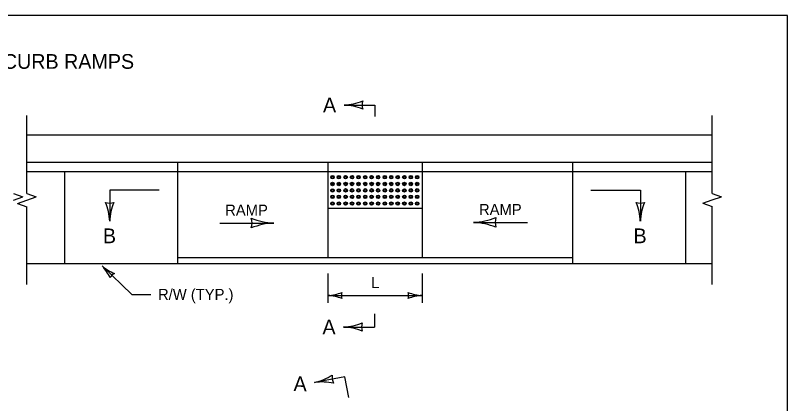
# Model space of a CAD drawing. Extents: x 49991.4 to 50021, y 49987.6 to 50011.4.
# Drawn here: x 50004.419 to 50008.615, y 50009.154 to 50011.263 of the extents above; entities that cross this region are included whole.
import ezdxf

# ---------------------------------------------------------------- set-up
doc = ezdxf.new("R2010")
doc.units = 0
for name, color, linetype in [('Level 1', 7, 'Continuous'), ('Level 2', 7, 'Continuous'), ('Level 3', 7, 'Continuous'), ('Level 6', 7, 'Continuous'), ('Level 8', 7, 'Continuous')]:
    doc.layers.add(name, color=color, linetype=linetype)

msp = doc.modelspace()

# ---------------------------------------------------------------- linework, layer by layer
at = {"layer": 'Level 1'}
for p, q in [((50008.2048, 50010.6129), (50004.4804, 50010.6129)), ((50008.2048, 50010.4629), (50004.4804, 50010.4629)), ((50005.2998, 50010.4629), (50005.2998, 50009.9129)), ((50006.1169, 50010.4629), (50006.117, 50009.9462)), ((50006.6283, 50010.4629), (50006.6284, 50009.9462)), ((50007.4459, 50010.4629), (50007.4458, 50009.9129)), ((50008.2048, 50010.4129), (50004.4804, 50010.4129)), ((50004.6865, 50009.9129), (50004.6863, 50010.4129)), ((50008.0591, 50010.4129), (50008.0591, 50009.9129)), ((50006.6283, 50010.2129), (50006.1169, 50010.2129)), ((50007.4458, 50009.9462), (50005.2998, 50009.9462)), ((50008.2048, 50009.9129), (50004.4804, 50009.9129))]:
    msp.add_line(p, q, dxfattribs=at)
msp.add_lwpolyline([(50008.6146, 50011.2628), (50000.3356, 50011.2628), (50000.3356, 50000.0624), (50008.6146, 50000.0624)], close=True, dxfattribs=at)
for points in [[(50008.6146, 50011.2628), (50000.3356, 50011.2628)], [(50008.6146, 50000.0624), (50008.6146, 50011.2628)]]:
    msp.add_lwpolyline(points, dxfattribs=at)
at = {"layer": 'Level 2'}
for centre in [(50006.3196, 50010.3122), (50006.3545, 50010.3122), (50006.3894, 50010.3122)]:
    msp.add_circle(centre, 0.00945, dxfattribs=at)
at = {"layer": 'Level 3'}
for p, q in [((50004.8898, 50009.9014), (50005.0518, 50009.7472)), ((50006.1171, 50009.8615), (50006.1171, 50009.7011)), ((50006.6285, 50009.8615), (50006.6285, 50009.7011)), ((50005.0518, 50009.7472), (50005.1536, 50009.7472)), ((50006.1171, 50009.7411), (50006.6285, 50009.7411))]:
    msp.add_line(p, q, dxfattribs=at)
for centre, radius, start, end in [((50006.1926, 50011.0723), 0.2964, 272.3605, 292.544), ((50006.1895, 50010.4658), 0.3107, 67.9228, 87.1727), ((50006.3758, 50010.7761), 0.073, 162.1388, 197.8612), ((50004.6348, 50010.133), 0.2964, 2.3605, 22.544), ((50004.931, 50010.3161), 0.073, 252.1388, 287.8612), ((50005.2413, 50010.1299), 0.3107, 157.9228, 177.1727), ((50007.5184, 50010.133), 0.2964, 2.3605, 22.544), ((50007.8146, 50010.3161), 0.073, 252.1388, 287.8612), ((50008.1249, 50010.1299), 0.3107, 157.9228, 177.1727), ((50005.6169, 50010.1348), 0.0876, 342.1388, 17.8612), ((50005.8404, 50010.5071), 0.3728, 247.9228, 267.1727), ((50006.8936, 50010.4938), 0.3557, 272.3605, 292.544), ((50007.1134, 50010.1384), 0.0876, 162.1388, 197.8612), ((50005.8367, 50009.7794), 0.3557, 92.3605, 112.544), ((50006.8898, 50009.766), 0.3728, 67.9228, 87.1727), ((50005.0363, 50010.0686), 0.2223, 228.7655, 248.949), ((50004.721, 50009.7408), 0.233, 24.3279, 43.5777), ((50004.9826, 50009.813), 0.0548, 118.5439, 154.2662), ((50006.1056, 50009.9738), 0.233, 272.8273, 292.0772), ((50006.1079, 50009.519), 0.2223, 67.456, 87.6395), ((50006.2453, 50009.7411), 0.0548, 162.1388, 197.8612), ((50006.6376, 50009.9632), 0.2223, 247.456, 267.6395), ((50006.5002, 50009.7411), 0.0548, 342.1388, 17.8612), ((50006.6399, 50009.5084), 0.233, 92.8273, 112.0772), ((50006.1896, 50009.8661), 0.2964, 272.3605, 292.544), ((50006.1865, 50009.2596), 0.3107, 67.9228, 87.1727), ((50006.3727, 50009.5699), 0.073, 162.1388, 197.8612), ((50005.9784, 50009.5575), 0.2964, 282.8123, 302.9958), ((50006.2123, 50009.2995), 0.073, 172.5907, 208.313), ((50006.0854, 50008.9605), 0.3107, 78.3747, 97.6245)]:
    msp.add_arc(centre, radius, start, end, dxfattribs=at)
at = {"layer": 'Level 6'}
for p, q in [((50006.2048, 50010.7761), (50006.3725, 50010.7761)), ((50006.3725, 50010.7761), (50006.3725, 50010.7129)), ((50004.4804, 50010.296), (50004.4804, 50010.7183)), ((50008.2048, 50010.2962), (50008.2048, 50010.7183)), ((50005.1143, 50010.3129), (50004.931, 50010.3129)), ((50004.931, 50010.3129), (50004.931, 50010.1452)), ((50005.1998, 50010.3129), (50004.931, 50010.3129)), ((50004.931, 50010.3129), (50004.931, 50010.1452)), ((50007.5459, 50010.3129), (50007.8146, 50010.3129)), ((50007.8146, 50010.3129), (50007.8146, 50010.1452)), ((50007.8146, 50010.3129), (50007.8146, 50010.1452)), ((50004.4081, 50010.296), (50004.4589, 50010.2778)), ((50004.4081, 50010.2598), (50004.4589, 50010.2778)), ((50004.4804, 50010.296), (50004.5312, 50010.2778)), ((50004.4804, 50010.2598), (50004.5312, 50010.2778)), ((50008.2048, 50010.2962), (50008.2556, 50010.278)), ((50008.2048, 50010.26), (50008.2556, 50010.278)), ((50004.4294, 50010.2417), (50004.4804, 50010.2598)), ((50004.4294, 50010.2417), (50004.4804, 50010.2237)), ((50008.1538, 50010.2419), (50008.2048, 50010.26)), ((50008.1538, 50010.2419), (50008.2048, 50010.2239)), ((50004.4804, 50009.8014), (50004.4804, 50010.2237)), ((50008.2048, 50009.8017), (50008.2048, 50010.2239)), ((50005.5289, 50010.1348), (50005.822, 50010.1348)), ((50006.9082, 50010.1384), (50007.2013, 50010.1384)), ((50006.3695, 50009.6411), (50006.3695, 50009.5699)), ((50006.2018, 50009.5699), (50006.3695, 50009.5699)), ((50006.2091, 50009.2989), (50006.0441, 50009.2684)), ((50006.2296, 50009.1876), (50006.2091, 50009.2989))]:
    msp.add_line(p, q, dxfattribs=at)
at = {"layer": 'Level 8'}
for centre, radius in [((50006.1414, 50010.3838), 0.00945), ((50006.1414, 50010.347), 0.00945), ((50006.1414, 50010.3838), 0.00525), ((50006.1763, 50010.3838), 0.00945), ((50006.1763, 50010.347), 0.00945), ((50006.1763, 50010.3838), 0.00525), ((50006.213, 50010.3838), 0.00945), ((50006.2131, 50010.3471), 0.00945), ((50006.213, 50010.3838), 0.00525), ((50006.2479, 50010.3838), 0.00945), ((50006.248, 50010.3471), 0.00945), ((50006.2479, 50010.3838), 0.00525), ((50006.2828, 50010.3838), 0.00945), ((50006.2828, 50010.3471), 0.00945), ((50006.2828, 50010.3838), 0.00525), ((50006.3196, 50010.3471), 0.00945), ((50006.3197, 50010.3837), 0.00945), ((50006.3197, 50010.3837), 0.00525), ((50006.3545, 50010.3839), 0.00945), ((50006.3545, 50010.3471), 0.00945), ((50006.3545, 50010.3839), 0.00525), ((50006.3894, 50010.3839), 0.00945), ((50006.3894, 50010.3471), 0.00945), ((50006.3894, 50010.3839), 0.00525), ((50006.4261, 50010.3839), 0.00945), ((50006.4261, 50010.3471), 0.00945), ((50006.4261, 50010.3839), 0.00525), ((50006.461, 50010.3839), 0.00945), ((50006.461, 50010.3471), 0.00945), ((50006.461, 50010.3839), 0.00525), ((50006.4959, 50010.3839), 0.00945), ((50006.4959, 50010.3472), 0.00945), ((50006.4959, 50010.3839), 0.00525), ((50006.5322, 50010.3838), 0.00945), ((50006.5322, 50010.347), 0.00945), ((50006.5322, 50010.3838), 0.00525), ((50006.5671, 50010.3838), 0.00945), ((50006.5671, 50010.3471), 0.00945), ((50006.5671, 50010.3838), 0.00525), ((50006.602, 50010.3838), 0.00945), ((50006.602, 50010.3471), 0.00945), ((50006.602, 50010.3838), 0.00525), ((50006.1414, 50010.3121), 0.00945), ((50006.1414, 50010.347), 0.00525), ((50006.1414, 50010.3121), 0.00525), ((50006.1763, 50010.3121), 0.00945), ((50006.1763, 50010.347), 0.00525), ((50006.1763, 50010.3121), 0.00525), ((50006.2131, 50010.3122), 0.00945), ((50006.2131, 50010.3471), 0.00525), ((50006.2131, 50010.3122), 0.00525), ((50006.248, 50010.3122), 0.00945), ((50006.248, 50010.3471), 0.00525), ((50006.248, 50010.3122), 0.00525), ((50006.2829, 50010.3122), 0.00945), ((50006.2828, 50010.3471), 0.00525), ((50006.2829, 50010.3122), 0.00525), ((50006.3196, 50010.3471), 0.00525), ((50006.3196, 50010.3122), 0.00525), ((50006.3545, 50010.3471), 0.00525), ((50006.3545, 50010.3122), 0.00525), ((50006.3894, 50010.3471), 0.00525), ((50006.3894, 50010.3122), 0.00525), ((50006.4261, 50010.3122), 0.00945), ((50006.4261, 50010.3471), 0.00525), ((50006.4261, 50010.3122), 0.00525), ((50006.461, 50010.3122), 0.00945), ((50006.461, 50010.3471), 0.00525), ((50006.461, 50010.3122), 0.00525), ((50006.4959, 50010.3123), 0.00945), ((50006.4959, 50010.3472), 0.00525), ((50006.4959, 50010.3123), 0.00525), ((50006.5322, 50010.3121), 0.00945), ((50006.5322, 50010.347), 0.00525), ((50006.5322, 50010.3121), 0.00525), ((50006.5671, 50010.3122), 0.00945), ((50006.5671, 50010.3471), 0.00525), ((50006.5671, 50010.3122), 0.00525), ((50006.602, 50010.3122), 0.00945), ((50006.602, 50010.3471), 0.00525), ((50006.602, 50010.3122), 0.00525), ((50006.1414, 50010.2772), 0.00945), ((50006.1414, 50010.2772), 0.00525), ((50006.1763, 50010.2772), 0.00945), ((50006.1763, 50010.2772), 0.00525), ((50006.2131, 50010.2773), 0.00945), ((50006.2131, 50010.2773), 0.00525), ((50006.248, 50010.2773), 0.00945), ((50006.248, 50010.2773), 0.00525), ((50006.2829, 50010.2773), 0.00945), ((50006.2829, 50010.2773), 0.00525), ((50006.3196, 50010.2773), 0.00945), ((50006.3196, 50010.2773), 0.00525), ((50006.3545, 50010.2773), 0.00945), ((50006.3545, 50010.2773), 0.00525), ((50006.3894, 50010.2773), 0.00945), ((50006.3894, 50010.2773), 0.00525), ((50006.4262, 50010.2773), 0.00945), ((50006.4262, 50010.2773), 0.00525), ((50006.4611, 50010.2774), 0.00945), ((50006.4611, 50010.2774), 0.00525), ((50006.4959, 50010.2774), 0.00945), ((50006.4959, 50010.2774), 0.00525), ((50006.5322, 50010.2772), 0.00945), ((50006.5322, 50010.2772), 0.00525), ((50006.5671, 50010.2773), 0.00945), ((50006.5671, 50010.2773), 0.00525), ((50006.602, 50010.2773), 0.00945), ((50006.602, 50010.2773), 0.00525), ((50006.1415, 50010.2405), 0.00945), ((50006.1415, 50010.2405), 0.00525), ((50006.1763, 50010.2405), 0.00945), ((50006.1763, 50010.2405), 0.00525), ((50006.2131, 50010.2405), 0.00945), ((50006.2131, 50010.2405), 0.00525), ((50006.248, 50010.2405), 0.00945), ((50006.248, 50010.2405), 0.00525), ((50006.2829, 50010.2405), 0.00945), ((50006.2829, 50010.2405), 0.00525), ((50006.3196, 50010.2405), 0.00945), ((50006.3196, 50010.2406), 0.00525), ((50006.3545, 50010.2406), 0.00945), ((50006.3545, 50010.2406), 0.00525), ((50006.3894, 50010.2406), 0.00945), ((50006.3894, 50010.2406), 0.00525), ((50006.4262, 50010.2406), 0.00945), ((50006.4262, 50010.2406), 0.00525), ((50006.4611, 50010.2406), 0.00945), ((50006.4611, 50010.2406), 0.00525), ((50006.496, 50010.2406), 0.00945), ((50006.496, 50010.2406), 0.00525), ((50006.5322, 50010.2405), 0.00945), ((50006.5322, 50010.2405), 0.00525), ((50006.5671, 50010.2405), 0.00945), ((50006.5671, 50010.2405), 0.00525), ((50006.602, 50010.2405), 0.00945), ((50006.602, 50010.2405), 0.00525)]:
    msp.add_circle(centre, radius, dxfattribs=at)

# ---------------------------------------------------------------- texts
at = {"layer": 'Level 2'}
for s, height, p in [('PARALLEL CURB RAMPS', 0.08, (50003.7794, 50010.9728)), ('A', 0.08, (50006.0901, 50010.7361)), ('RAMP', 0.06, (50005.5586, 50010.1748)), ('RAMP', 0.06, (50006.9379, 50010.1784)), ('B', 0.08, (50004.894, 50010.0252)), ('B', 0.08, (50007.7776, 50010.0252)), ('L', 0.06, (50006.3516, 50009.7811)), ('R/W (TYP.)', 0.06, (50005.1936, 50009.7172)), ('A', 0.08, (50006.087, 50009.5299))]:
    msp.add_text(s, height=height, dxfattribs=at).set_placement(p)
msp.add_text('A', height=0.08, rotation=359.5801, dxfattribs=at).set_placement((50005.9298, 50009.2217))

doc.saveas('drawing.dxf')
